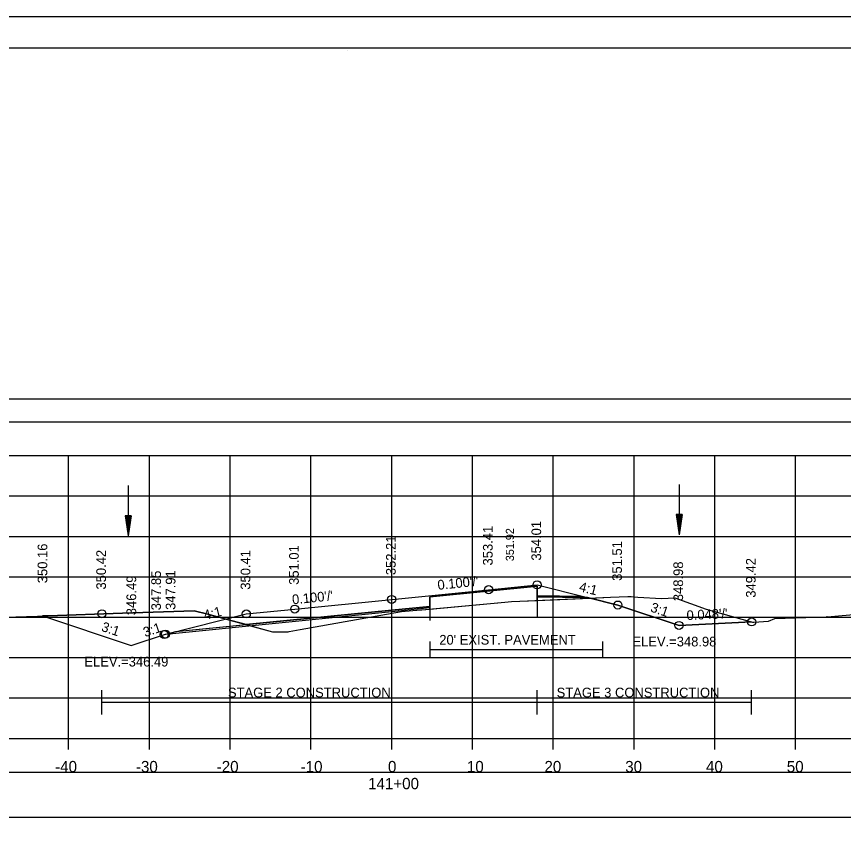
# Model space of a CAD drawing. Extents: x 1376273 to 1384221, y 378927 to 384592.
# Drawn here: x 1377011.3 to 1377113.7, y 382357.1 to 382458.6 of the extents above; entities that cross this region are included whole.
import ezdxf

# ---------------------------------------------------------------- set-up
doc = ezdxf.new("R2010")
doc.units = 0
for name, color, linetype in [('R_Alt Surface', 7, 'Continuous'), ('R_Axis', 7, 'Continuous'), ('R_Axis Annot', 7, 'Continuous'), ('R_Border', 7, 'Continuous'), ('R_Border Notes', 7, 'Continuous'), ('R_Dimension', 7, 'Continuous'), ('R_Exist Surface', 7, 'Continuous'), ('R_Fin Surface', 7, 'Continuous'), ('R_Grid', 7, 'Continuous'), ('R_No Plot', 7, 'Continuous'), ('R_Water', 7, 'Continuous'), ('R_Xsect Elev', 7, 'Continuous'), ('R_Xsect Slope', 7, 'Continuous'), ('T_Detection Zones', 7, 'Continuous'), ('T_Vehicle Path Lt Minor', 7, 'Continuous')]:
    doc.layers.add(name, color=color, linetype=linetype)

msp = doc.modelspace()

# ---------------------------------------------------------------- linework, layer by layer
at = {"layer": 'R_Alt Surface'}
for points in [[(1377031.04, 382382.42), (1377057.77, 382385.07), (1377062.51, 382385.54), (1377062.51, 382386.71), (1377075.77, 382388.04), (1377075.78, 382386.87), (1377081.33, 382386.81)], [(1377062.51, 382381.19), (1377062.51, 382379.19)], [(1377083.85, 382381.19), (1377083.85, 382379.19)], [(1377062.51, 382380.19), (1377083.85, 382380.19)]]:
    msp.add_lwpolyline(points, dxfattribs=at)
at = {"layer": 'R_Axis'}
for p, q in [((1376907.77, 382369.2), (1377207.77, 382369.2)), ((1377017.77, 382367.8), (1377017.77, 382369.2)), ((1377027.77, 382367.8), (1377027.77, 382369.2)), ((1377037.77, 382367.8), (1377037.77, 382369.2)), ((1377047.77, 382367.8), (1377047.77, 382369.2)), ((1377057.77, 382367.8), (1377057.77, 382369.2)), ((1377067.77, 382367.8), (1377067.77, 382369.2)), ((1377077.77, 382367.8), (1377077.77, 382369.2)), ((1377087.77, 382367.8), (1377087.77, 382369.2)), ((1377097.77, 382367.8), (1377097.77, 382369.2)), ((1377107.77, 382367.8), (1377107.77, 382369.2))]:
    msp.add_line(p, q, dxfattribs=at)
at = {"layer": 'R_Axis Annot'}
for points in [[(1376907.2, 382408.38), (1377209.01, 382408.38), (1377209.01, 382411.2), (1376907.2, 382411.2)], [(1376907.2, 382359.43), (1377209.01, 382359.43), (1377209.01, 382364.95), (1376907.2, 382364.95)]]:
    msp.add_lwpolyline(points, close=True, dxfattribs=at)
at = {"layer": 'R_Border'}
for p, q in [((1376899.77, 382454.66), (1377215.95, 382454.66)), ((1377052.29, 382454.4), (1377052.29, 382454.4)), ((1377052.29, 382454.4), (1377052.29, 382454.4))]:
    msp.add_line(p, q, dxfattribs=at)
at = {"layer": 'R_Dimension'}
for p, q in [((1377021.9, 382372.17), (1377021.9, 382375.17)), ((1377075.78, 382372.17), (1377075.78, 382375.17)), ((1377102.33, 382372.17), (1377102.33, 382375.17)), ((1377021.9, 382373.67), (1377102.33, 382373.67))]:
    msp.add_line(p, q, dxfattribs=at)
at = {"layer": 'R_Exist Surface'}
msp.add_lwpolyline([(1377009.9, 382384.21), (1377015.23, 382384.38), (1377024.44, 382384.71), (1377033.31, 382385), (1377035.03, 382384.56), (1377043.03, 382382.4), (1377044.93, 382382.39), (1377044.95, 382382.39), (1377045.09, 382382.42), (1377046.44, 382382.66), (1377059, 382384.92), (1377061.32, 382385.09), (1377061.51, 382385.11), (1377071.77, 382386.05), (1377072.6, 382386.12), (1377073.65, 382386.18), (1377084.85, 382386.68), (1377087.02, 382386.76), (1377087.43, 382386.77), (1377088.23, 382386.67), (1377091.18, 382386.53), (1377092.84, 382386.59), (1377096.69, 382385.17), (1377102.14, 382383.66), (1377102.45, 382383.59), (1377102.49, 382383.57), (1377102.59, 382383.57), (1377104.41, 382383.72), (1377105.22, 382384.04), (1377111.58, 382384.26), (1377111.67, 382384.27), (1377111.71, 382384.26), (1377125.01, 382385.42)], dxfattribs=at)
at = {"layer": 'R_Fin Surface'}
msp.add_lwpolyline([(1377014.54, 382384.36), (1377025.54, 382380.69), (1377029.77, 382382.1), (1377029.8, 382382.11), (1377039.77, 382384.6), (1377045.77, 382385.2), (1377057.77, 382386.4), (1377069.77, 382387.6), (1377075.77, 382388.2), (1377082, 382386.64), (1377085.77, 382385.7), (1377093.34, 382383.18), (1377102.33, 382383.61)], dxfattribs=at)
at = {"layer": 'R_Grid'}
for p, q in [((1376907.77, 382404.2), (1377207.77, 382404.2)), ((1376907.77, 382404.2), (1377207.77, 382404.2)), ((1377017.77, 382369.2), (1377017.77, 382404.2)), ((1377017.77, 382369.2), (1377017.77, 382404.2)), ((1377027.77, 382369.2), (1377027.77, 382404.2)), ((1377027.77, 382369.2), (1377027.77, 382404.2)), ((1377037.77, 382369.2), (1377037.77, 382404.2)), ((1377037.77, 382369.2), (1377037.77, 382404.2)), ((1377047.77, 382369.2), (1377047.77, 382404.2)), ((1377047.77, 382369.2), (1377047.77, 382404.2)), ((1377057.77, 382369.2), (1377057.77, 382404.2)), ((1377057.77, 382369.2), (1377057.77, 382404.2)), ((1377067.77, 382369.2), (1377067.77, 382404.2)), ((1377067.77, 382369.2), (1377067.77, 382404.2)), ((1377077.77, 382369.2), (1377077.77, 382404.2)), ((1377077.77, 382369.2), (1377077.77, 382404.2)), ((1377087.77, 382369.2), (1377087.77, 382404.2)), ((1377087.77, 382369.2), (1377087.77, 382404.2)), ((1377097.77, 382369.2), (1377097.77, 382404.2)), ((1377097.77, 382369.2), (1377097.77, 382404.2)), ((1377107.77, 382369.2), (1377107.77, 382404.2)), ((1377107.77, 382369.2), (1377107.77, 382404.2)), ((1376907.77, 382399.2), (1377207.77, 382399.2)), ((1376907.77, 382399.2), (1377207.77, 382399.2)), ((1376907.77, 382394.2), (1377207.77, 382394.2)), ((1376907.77, 382394.2), (1377207.77, 382394.2)), ((1376907.77, 382389.2), (1377207.77, 382389.2)), ((1376907.77, 382389.2), (1377207.77, 382389.2)), ((1376907.77, 382384.2), (1377207.77, 382384.2)), ((1376907.77, 382384.2), (1377207.77, 382384.2)), ((1376907.77, 382379.2), (1377207.77, 382379.2)), ((1376907.77, 382379.2), (1377207.77, 382379.2)), ((1376907.77, 382374.2), (1377207.77, 382374.2)), ((1376907.77, 382374.2), (1377207.77, 382374.2)), ((1376907.77, 382369.2), (1377207.77, 382369.2)), ((1376907.77, 382369.2), (1377207.77, 382369.2))]:
    msp.add_line(p, q, dxfattribs=at)
at = {"layer": 'R_No Plot'}
msp.add_line((1376887.37, 382458.55), (1377220.7, 382458.55), dxfattribs=at)
for points in [[(1376887.36, 382458.55), (1377220.7, 382458.55), (1377220.7, 382245.22), (1376887.36, 382245.22)], [(1377133.69, 382454.66), (1377133.69, 382444.78), (1377169.42, 382444.78), (1377169.42, 382441.86), (1377192.62, 382441.86), (1377192.62, 382417.53), (1377215.95, 382417.53), (1377215.95, 382249.2), (1376899.77, 382249.2), (1376899.77, 382454.66)]]:
    msp.add_lwpolyline(points, close=True, dxfattribs=at)
msp.add_lwpolyline([(1377029.8, 382382.11), (1377057.77, 382384.9), (1377062.51, 382385.38), (1377062.51, 382386.71), (1377075.77, 382388.04), (1377075.78, 382386.71), (1377082, 382386.64)], dxfattribs=at)
for centre in [(1377075.77, 382388.2), (1377075.77, 382388.2), (1377069.77, 382387.6), (1377069.77, 382387.6), (1377057.77, 382386.4), (1377057.77, 382386.4), (1377045.77, 382385.2), (1377045.77, 382385.2), (1377085.77, 382385.7), (1377085.77, 382385.7), (1377021.9, 382384.62), (1377021.9, 382384.62), (1377039.77, 382384.6), (1377039.77, 382384.6), (1377093.34, 382383.18), (1377093.34, 382383.18), (1377093.34, 382383.18), (1377093.34, 382383.18), (1377102.33, 382383.61), (1377102.33, 382383.61), (1377029.61, 382382.05), (1377029.61, 382382.05), (1377029.61, 382382.05), (1377029.61, 382382.05), (1377029.77, 382382.1), (1377029.77, 382382.1)]:
    msp.add_circle(centre, 0.5, dxfattribs=at)
at = {"layer": 'R_Water'}
for p, q in [((1377025.15, 382400.51), (1377025.15, 382394.26)), ((1377093.34, 382400.64), (1377093.34, 382394.39)), ((1377092.97, 382396.89), (1377093.34, 382394.39)), ((1377093.72, 382396.89), (1377092.97, 382396.89)), ((1377093.03, 382396.89), (1377093.34, 382394.8)), ((1377093.1, 382396.89), (1377093.34, 382395.23)), ((1377093.16, 382396.89), (1377093.34, 382395.65)), ((1377093.22, 382396.89), (1377093.34, 382396.07)), ((1377093.29, 382396.89), (1377093.34, 382396.49)), ((1377093.72, 382396.89), (1377093.34, 382394.39)), ((1377093.47, 382396.89), (1377093.34, 382396.07)), ((1377093.59, 382396.89), (1377093.34, 382395.23)), ((1377093.66, 382396.89), (1377093.34, 382394.8)), ((1377093.53, 382396.89), (1377093.34, 382395.65)), ((1377093.4, 382396.89), (1377093.34, 382396.49)), ((1377024.78, 382396.76), (1377025.15, 382394.26)), ((1377025.53, 382396.76), (1377024.78, 382396.76)), ((1377024.84, 382396.76), (1377025.15, 382394.68)), ((1377024.9, 382396.76), (1377025.15, 382395.11)), ((1377024.97, 382396.76), (1377025.15, 382395.52)), ((1377025.03, 382396.76), (1377025.15, 382395.95)), ((1377025.09, 382396.76), (1377025.15, 382396.36)), ((1377025.53, 382396.76), (1377025.15, 382394.26)), ((1377025.27, 382396.76), (1377025.15, 382395.95)), ((1377025.4, 382396.76), (1377025.15, 382395.11)), ((1377025.46, 382396.76), (1377025.15, 382394.68)), ((1377025.34, 382396.76), (1377025.15, 382395.52)), ((1377025.21, 382396.76), (1377025.15, 382396.36))]:
    msp.add_line(p, q, dxfattribs=at)
at = {"layer": 'T_Detection Zones'}
for p, q in [((1377075.78, 382386.71), (1377075.78, 382384.16)), ((1377082, 382386.64), (1377075.78, 382386.71)), ((1377075.78, 382386.71), (1377075.78, 382386.27)), ((1377082.32, 382386.57), (1377082, 382386.64)), ((1377075.78, 382386.27), (1377082.32, 382386.57)), ((1377062.51, 382385.54), (1377062.51, 382383.78)), ((1377062.51, 382385.2), (1377062.51, 382385.54)), ((1377031.04, 382382.42), (1377039.75, 382383.28))]:
    msp.add_line(p, q, dxfattribs=at)
msp.add_lwpolyline([(1377082.32, 382386.57), (1377084.85, 382386.68), (1377087.02, 382386.76), (1377087.43, 382386.77), (1377088.23, 382386.67), (1377091.18, 382386.53), (1377092.84, 382386.59), (1377096.69, 382385.17), (1377102.14, 382383.66), (1377102.33, 382383.61), (1377093.34, 382383.18), (1377085.77, 382385.7)], close=True, dxfattribs=at)
for points in [[(1377039.75, 382383.28), (1377037.22, 382383.97), (1377035.03, 382384.56), (1377033.31, 382385), (1377024.44, 382384.71), (1377015.23, 382384.38), (1377014.54, 382384.36)], [(1377062.51, 382385.54), (1377057.77, 382385.07), (1377039.75, 382383.28)], [(1377039.75, 382383.28), (1377043.03, 382382.4), (1377044.93, 382382.39), (1377044.95, 382382.39), (1377045.09, 382382.42), (1377046.44, 382382.66), (1377059, 382384.92), (1377061.32, 382385.09), (1377061.51, 382385.11), (1377062.51, 382385.2)], [(1377014.54, 382384.36), (1377025.54, 382380.69), (1377029.77, 382382.1), (1377029.8, 382382.11), (1377031.04, 382382.42)]]:
    msp.add_lwpolyline(points, dxfattribs=at)
at = {"layer": 'T_Vehicle Path Lt Minor'}
for p, q in [((1377075.78, 382386.27), (1377075.78, 382386.71)), ((1377062.51, 382385.38), (1377062.51, 382385.2))]:
    msp.add_line(p, q, dxfattribs=at)
for points in [[(1377075.78, 382386.71), (1377075.77, 382388.04), (1377062.51, 382386.71), (1377062.51, 382385.38)], [(1377062.51, 382385.2), (1377071.77, 382386.05), (1377072.6, 382386.12), (1377073.65, 382386.18), (1377075.78, 382386.27)]]:
    msp.add_lwpolyline(points, dxfattribs=at)

# ---------------------------------------------------------------- texts
at = {"layer": 'R_Alt Surface'}
msp.add_text("20' EXIST. PAVEMENT", height=1.2, dxfattribs=at).set_placement((1377063.66, 382380.8))
at = {"layer": 'R_Axis Annot'}
for s, p in [('-40', (1377016.11, 382365)), ('-30', (1377026.11, 382365)), ('-20', (1377036.11, 382365)), ('-10', (1377046.5, 382365)), ('0', (1377057.31, 382365)), ('10', (1377067.08, 382365)), ('20', (1377076.68, 382365)), ('30', (1377086.68, 382365)), ('40', (1377096.68, 382365)), ('50', (1377106.68, 382365)), ('141+00', (1377054.85, 382362.9))]:
    msp.add_text(s, height=1.4, dxfattribs=at).set_placement(p)
at = {"layer": 'R_Border Notes'}
for s, p in [('ELEV.=348.98', (1377087.57, 382380.58)), ('ELEV.=346.49', (1377019.73, 382378.09))]:
    msp.add_text(s, height=1.2, dxfattribs=at).set_placement(p)
at = {"layer": 'R_Dimension'}
for s, p in [('STAGE 2 CONSTRUCTION', (1377037.5, 382374.27)), ('STAGE 3 CONSTRUCTION', (1377078.19, 382374.27))]:
    msp.add_text(s, height=1.2, dxfattribs=at).set_placement(p)
at = {"layer": 'R_No Plot'}
for s, p in [('350.42', (1377022.4, 382387.62)), ('347.85', (1377029.21, 382385.05))]:
    msp.add_text(s, height=1.2, rotation=90, dxfattribs=at).set_placement(p)
at = {"layer": 'R_Xsect Elev'}
for s, height, p in [('354.01', 1.2, (1377076.27, 382391.2)), ('353.41', 1.2, (1377070.27, 382390.6)), ('351.92', 1, (1377072.9, 382391.13)), ('352.21', 1.2, (1377058.27, 382389.4)), ('350.16', 1.2, (1377015.14, 382388.4)), ('351.01', 1.2, (1377046.27, 382388.2)), ('351.51', 1.2, (1377086.27, 382388.7)), ('350.41', 1.2, (1377040.27, 382387.6)), ('348.98', 1.2, (1377093.84, 382386.18)), ('349.42', 1.2, (1377102.83, 382386.61)), ('347.91', 1.2, (1377031, 382385.1)), ('346.49', 1.2, (1377026.14, 382384.44))]:
    msp.add_text(s, height=height, rotation=90, dxfattribs=at).set_placement(p)
at = {"layer": 'R_Xsect Slope'}
for s, rotation, p in [("0.100'/'", 5.7106, (1377063.5, 382387.58)), ('4:1', 345.9638, (1377080.89, 382387.44)), ("0.100'/'", 5.7106, (1377045.5, 382385.78)), ('3:1', 341.5651, (1377089.71, 382384.92)), ('4:1', 14.0362, (1377034.65, 382383.84)), ("0.048'/'", 2.7758, (1377094.3, 382383.83)), ('3:1', 341.5651, (1377021.74, 382382.52)), ('3:1', 18.4349, (1377027.24, 382381.72))]:
    msp.add_text(s, height=1.2, rotation=rotation, dxfattribs=at).set_placement(p)

doc.saveas('drawing.dxf')
